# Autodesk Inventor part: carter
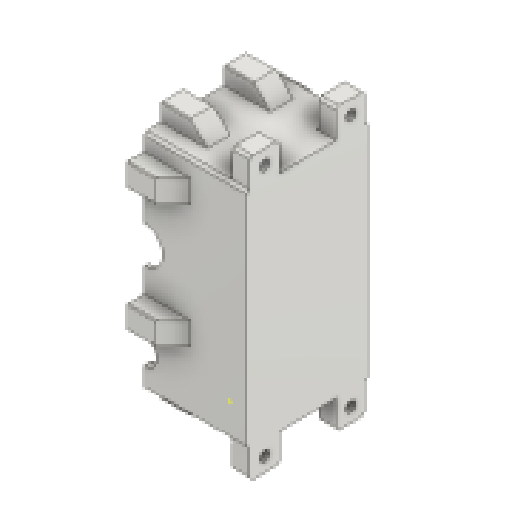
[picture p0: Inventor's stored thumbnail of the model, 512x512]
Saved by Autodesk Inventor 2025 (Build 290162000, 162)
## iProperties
Created: 2026-05
Part Number: carter
Material: Acciaio
Document SubType Name: Modeling
Designer: R5800u
Density: 7.85 g/cm^3
Appearance: Acciaio
Author: R5800u
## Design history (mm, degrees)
node "Piano di lavoro1"
sketch "Schizzo1"
  geometry: L1 (0, -58)-(160, -58); L2 (160, -58)-(160, 332); L3 (160, 332)-(0, 332); L4 (0, 332)-(0, -58); C1 r 12 at (0, 0) reference; C2 r 31 at (0, 0) reference; C3 r 45 at (0, 162) reference; A1 r 19.5 centre (0, 162) between (-18.561, 156.023) and (-18.547, 168.023) reference; 5 further points
  constraints: 8 end point, 2 parallel, 1 horizontal, 1 perpendicular
  dimensions: "d0" = 160 distance of L1.start L1.end; "d1" = 390 distance of L1.end L2.end
extrude "Estrusione1" new body sketch "Schizzo1" distance "d3" = 35; taper "d4" = 0 deg
node "Piano di lavoro2"
mirror "Speculare1"
sketch "Schizzo2"
  geometry: L1 (0, 390)-(35, 390) reference; L2 (210, 0)-(210, 390) reference; L3 (0, 390)-(210, 390); L4 (210, 390)-(210, 0); L5 (210, 0)-(0, 0); L6 (0, 0)-(0, 390); 3 further points
  constraints: 8 end point, 2 parallel, 1 horizontal, 1 perpendicular
extrude "Estrusione2" join sketch "Schizzo2" distance "d6" = 20; taper "d7" = 0 deg
sketch "Schizzo3"
  geometry: L1 (-175, 390)-(-35, 390) reference; L2 (-175, 390)-(-175, 0) reference; L3 (-35, 390)-(-175, 390); L4 (-175, 390)-(-175, 370); L5 (-175, 370)-(-35, 370); L6 (-35, 370)-(-35, 390); L7 (0, 0)-(-35, 0) reference; L8 (-35, 0)-(-175, 0); L9 (-175, 0)-(-175, 20); L10 (-175, 20)-(-35, 20); L11 (-35, 20)-(-35, 0); 2 further points
  constraints: 16 end point, 4 parallel, 2 horizontal, 2 perpendicular, 2 point on line
  dimensions: "d8" = 20 distance of L4.end L3.end; "d9" = 20 distance of L8.end L9.end
extrude "Estrusione3" join sketch "Schizzo3" stored distance "d10" = 20; taper "d11" = 0 deg
sketch "Schizzo4"
  geometry: L1 (0, 170)-(0, 45) reference; L2 (0, 170)-(-180, 170) reference; L3 (-180, -220)-(-180, 170) reference; L4 (0, -220)-(-180, -220) reference; L5 (0, -193)-(0, -220) reference; L6 (0, -45)-(0, -131) reference; L7 (0, 45)-(0, -45); C1 r 32.5 at (0, 0); A1 r 31 centre (0, -162) between (0, -131) and (0, -193) reference; A2 r 45 centre (0, 0) between (0, 45) and (0, -45) reference; 3 further points
  constraints: 2 end point, 1 centre point, 1 coincident, 1 vertical
  dimensions: "d12" = 65 diameter of C1
  node "Linea chiusa proiettata1"
node "Piano di lavoro3"
extrude "Estrusione4" join sketch "Schizzo4" stored distance "d13" = 10; taper "d14" = 0 deg
sketch "Schizzo5"
  geometry: L1 (0, 332)-(0, 194.5) reference; L2 (0, 332)-(-180, 332) reference; L3 (-180, -58)-(-180, 332) reference; L4 (0, -58)-(-180, -58) reference; L5 (0, -31)-(0, -58) reference; L6 (0, 31)-(0, 129.5) reference; L7 (0, 31)-(0, -31); C1 r 21 at (-1.789, 0); A1 r 31 centre (0, 0) between (0, 31) and (0, -31) reference; A2 r 32.5 centre (0, 162) between (0, 194.5) and (0, 129.5) reference; 3 further points
  constraints: 2 end point, 1 centre point, 1 collinear
  dimensions: "d15" = 42 diameter of C1
  node "Linea chiusa proiettata2"
node "Piano di lavoro4"
extrude "Estrusione5" join sketch "Schizzo5" stored distance "d16" = 10; taper "d17" = 0 deg
mirror "Speculare2"
chamfer "Smusso1" distance "d18" = 5; stored, may be unused: second distance "d19" = 2, angle "d20" = 45 deg
sketch "Schizzo6"
  geometry: L1 (-35, 120)-(-30, 125) reference; L2 (-35, 120)-(-35, -12.5) reference; L3 (-35, -12.5)-(-28, -12.5) reference; L4 (-28, 0)-(-28, -12.5) reference; L5 (-28, 0)-(0, 0) reference; L6 (0, 0)-(0, 105) reference; L7 (140, 105)-(0, 105) reference; L8 (140, 0)-(140, 105) reference; L9 (168, 0)-(140, 0) reference; L10 (168, 0)-(168, -12.5) reference; L11 (175, -12.5)-(168, -12.5) reference; L12 (175, 120)-(175, -12.5) reference; L13 (170, 125)-(175, 120) reference; L14 (170, 125)-(-30, 125) reference; L15 (175, -260)-(170, -265) reference; L16 (175, -227.924)-(175, -260) reference; L17 (175, -227.924)-(162, -227.924) reference; L18 (162, -227.924)-(162, -238) reference; L19 (162, -238)-(140, -238) reference; L20 (140, -245)-(140, -238) reference; L21 (0, -245)-(140, -245) reference; L22 (0, -245)-(0, -238) reference; L23 (-22, -238)-(0, -238) reference; L24 (-22, -227.924)-(-22, -238) reference; L25 (-35, -227.924)-(-22, -227.924) reference; L26 (-35, -260)-(-35, -227.924) reference; L27 (-30, -265)-(-35, -260) reference; L28 (170, -265)-(-30, -265) reference; L29 (175, -77.5)-(175, -186.076) reference; L30 (175, -77.5)-(168, -77.5) reference; L31 (168, -77.5)-(168, -90) reference; L32 (168, -90)-(140, -90) reference; L33 (140, -176)-(140, -90) reference; L34 (162, -176)-(140, -176) reference; L35 (162, -176)-(162, -186.076) reference; L36 (175, -186.076)-(162, -186.076) reference; L37 (-35, -186.076)-(-35, -77.5) reference; L38 (-35, -186.076)-(-22, -186.076) reference; L39 (-22, -176)-(-22, -186.076) reference; L40 (-22, -176)-(0, -176) reference; L41 (0, -176)-(0, -90) reference; L42 (-28, -90)-(0, -90) reference; L43 (-28, -77.5)-(-28, -90) reference; L44 (-35, -77.5)-(-28, -77.5) reference; L45 (125, 125)-(125, -265); L46 (-30, 125)-(170, 125) reference; L47 (70, 125)-(70, -265); L48 (15, 125)-(15, -265); L49 (175, 75)-(-35, 75); L50 (-35, -260)-(-35, 120) reference; L51 (145, 95)-(205, 95); L52 (205, 95)-(205, 55); L53 (205, 55)-(145, 55); L54 (145, 55)-(145, 95); L55 (145, 95)-(205, 55); L56 (205, 95)-(145, 55); L57 (145, -235)-(105, -235); L58 (105, -235)-(105, -295); L59 (105, -295)-(145, -295); L60 (145, -295)-(145, -235); L61 (145, -235)-(105, -295); L62 (105, -235)-(145, -295); L63 (35, -235)-(-5, -235); L64 (-5, -235)-(-5, -295)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; 16 further points
  constraints: 106 end point, 18 midpoint, 16 parallel, 11 perpendicular, 8 horizontal, 6 point on line, 2 symmetric about line
  dimensions: "d21" = 50 distance between parallel lines of L12 L45; "d22" = 50 distance between parallel lines of L14 L49; "d23" = 60 distance of L52.end L53.end; "d24" = 40 distance of L51.end L52.end; "d29" = 40 distance of L59.end L58.end; "d30" = 60 distance of L58.end L57.end; "d31" = 40 distance of L65.end L64.end; "d32" = 60 distance of L64.end L63.end; "d33" = 40 distance of L71.end L70.end; "d34" = 60 distance of L70.end L69.end; "d35" = 60 distance of L77.end L76.end; "d36" = 40 distance of L76.end L75.end; "d41" = 40 distance of L83.end L82.end; "d42" = 60 distance of L82.end L81.end; "d43" = 60 distance of L90.end L91.end; "d44" = 40 distance of L89.end L90.end; "d45" = 60 distance of L97.end L96.end; "d46" = 40 distance of L96.end L95.end; "d47" = 125 distance between parallel lines of L28 L88
extrude "Estrusione6" join sketch "Schizzo6" distance "d48" = 50; taper "d49" = 0 deg
chamfer "Smusso2" distance "d50" = 30; stored, may be unused: second distance "d51" = 2, angle "d52" = 45 deg
sketch "Schizzo7"
  geometry: L1 (-35, 120)-(-30, 125) reference; L2 (-35, 120)-(-35, 95) reference; L3 (-35, 95)-(-65, 95) reference; L4 (-65, 95)-(-65, 55) reference; L5 (-65, 55)-(-35, 55) reference; L6 (-35, 55)-(-35, -12.5) reference; L7 (-35, -12.5)-(-28, -12.5) reference; L8 (-28, 0)-(-28, -12.5) reference; L9 (-28, 0)-(0, 0) reference; L10 (0, 0)-(0, 105) reference; L11 (140, 105)-(0, 105) reference; L12 (140, 0)-(140, 105) reference; L13 (168, 0)-(140, 0) reference; L14 (168, 0)-(168, -12.5) reference; L15 (175, -12.5)-(168, -12.5) reference; L16 (175, 55)-(175, -12.5) reference; L17 (175, 55)-(205, 55) reference; L18 (205, 55)-(205, 95) reference; L19 (205, 95)-(175, 95) reference; L20 (175, 120)-(175, 95) reference; L21 (170, 125)-(175, 120) reference; L22 (170, 125)-(145, 125) reference; L23 (145, 125)-(145, 155) reference; L24 (145, 155)-(105, 155) reference; L25 (105, 155)-(105, 125) reference; L26 (105, 125)-(35, 125) reference; L27 (35, 125)-(35, 155) reference; L28 (35, 155)-(-5, 155) reference; L29 (-5, 155)-(-5, 125) reference; L30 (-5, 125)-(-30, 125) reference; L31 (-35, -186.076)-(-35, -160) reference; L32 (-35, -186.076)-(-22, -186.076) reference; L33 (-22, -176)-(-22, -186.076) reference; L34 (-22, -176)-(0, -176) reference; L35 (0, -176)-(0, -90) reference; L36 (-28, -90)-(0, -90) reference; L37 (-28, -77.5)-(-28, -90) reference; L38 (-35, -77.5)-(-28, -77.5) reference; L39 (-35, -120)-(-35, -77.5) reference; L40 (-35, -120)-(-65, -120) reference; L41 (-65, -120)-(-65, -160) reference; L42 (-65, -160)-(-35, -160) reference; L43 (-5, -265)-(35, -265) reference; L44 (175, -260)-(170, -265) reference; L45 (175, -227.924)-(175, -260) reference; L46 (175, -227.924)-(162, -227.924) reference; L47 (162, -227.924)-(162, -238) reference; L48 (162, -238)-(140, -238) reference; L49 (140, -245)-(140, -238) reference; L50 (0, -245)-(140, -245) reference; L51 (0, -245)-(0, -238) reference; L52 (-22, -238)-(0, -238) reference; L53 (-22, -227.924)-(-22, -238) reference; L54 (-35, -227.924)-(-22, -227.924) reference; L55 (-35, -260)-(-35, -227.924) reference; L56 (-30, -265)-(-35, -260) reference; L57 (-5, -265)-(-30, -265) reference; L58 (-5, -265)-(-5, -295) reference; L59 (-5, -295)-(35, -295) reference; L60 (35, -295)-(35, -265) reference; L61 (105, -265)-(35, -265) reference; L62 (105, -265)-(105, -295) reference; L63 (105, -295)-(145, -295) reference; L64 (145, -295)-(145, -265) reference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; 9 further points
  constraints: 16 end point, 8 midpoint, 2 parallel
hole "Foro1" sketch "Schizzo7" at (15, -280), (125, -280), (190, -140), (-50, -140), (-50, 75), (15, 140), (125, 140), (190, 75) diameter "d53" = 10.106; stored, may be unused: countersink angle "d57" = 82 deg, drill point angle "d59" = 118 deg; dims "d54" = 24, "d55" = 3.023, "d56" = 2, "d58" = 32.3
sketch "Schizzo8"
  geometry: L1 (160, 30)-(160, 170) reference; L2 (160, 100)-(144, 100); 1 further point
  constraints: 2 end point, 1 horizontal, 1 midpoint
  dimensions: "d60" = 16 distance of L2.start L2.end
hole "Foro2" sketch "Schizzo8" at (144, 100) diameter "d61" = 29.83494; stored, may be unused: countersink angle "d65" = 90 deg, drill point angle "d67" = 118 deg; dims "d62" = 64, "d63" = 4, "d64" = 2, "d66" = 73.3
chamfer "Smusso3" distance "d68" = 2; stored, may be unused: second distance "d69" = 2, angle "d70" = 45 deg
chamfer "Smusso4" distance "d71" = 0.4; stored, may be unused: second distance "d72" = 2, angle "d73" = 45 deg
sketch "Schizzo9"
  geometry: L1 (205, 390)-(210, 385) reference; L2 (205, 390)-(5, 390) reference; L3 (0, 385)-(5, 390) reference; L4 (0, 385)-(0, 5) reference; L5 (5, 0)-(0, 5) reference; L6 (5, 0)-(205, 0) reference; L7 (210, 5)-(205, 0) reference; L8 (210, 5)-(210, 385) reference; L9 (205, 0)-(155, 0); L10 (155, 0)-(155, -50); L11 (155, -50)-(205, -50); L12 (205, -50)-(205, 0); L13 (5, 0)-(55, 0); L14 (55, 0)-(55, -50); L15 (55, -50)-(5, -50); L16 (5, -50)-(5, 0); L17 (205, 390)-(155, 390); L18 (155, 390)-(155, 440); L19 (155, 440)-(205, 440); L20 (205, 440)-(205, 390); L21 (5, 390)-(55, 390); L22 (55, 390)-(55, 440); L23 (55, 440)-(5, 440); L24 (5, 440)-(5, 390); 5 further points
  constraints: 32 end point, 8 parallel, 4 horizontal, 4 perpendicular, 2 point on line
  dimensions: "d74" = 50 distance of L11.end L10.end; "d75" = 50 distance of L10.end L9.end; "d76" = 50 distance of L18.end L19.end; "d77" = 50 distance of L17.end L18.end; "d78" = 50 distance of L23.end L22.end; "d79" = 50 distance of L22.end L21.end
extrude "Estrusione7" join sketch "Schizzo9" distance "d80" = 30; taper "d81" = 0 deg
sketch "Schizzo10"
  geometry: 1 further point
sketch "Schizzo11"
  geometry: L1 (-205, 0)-(-205, -50) reference; L2 (-205, -50)-(-155, -50) reference; L3 (-155, -50)-(-155, 0) reference; L4 (-205, 0)-(-155, 0) reference; L5 (-155, 440)-(-205, 440) reference; L6 (-205, 440)-(-205, 390) reference; L7 (-155, 390)-(-205, 390) reference; L8 (-155, 390)-(-155, 440) reference; L9 (-5, 390)-(-5, 440) reference; L10 (-5, 440)-(-55, 440) reference; L11 (-55, 440)-(-55, 390) reference; L12 (-5, 390)-(-55, 390) reference; L13 (-55, -50)-(-5, -50) reference; L14 (-5, -50)-(-5, 0) reference; L15 (-55, 0)-(-5, 0) reference; L16 (-55, 0)-(-55, -50) reference; L17 (-205, 0)-(-155, -50); L18 (-55, -50)-(-5, 0); L19 (-155, 440)-(-205, 390); L20 (-55, 440)-(-5, 390); 5 further points
  constraints: 8 end point, 4 midpoint, 2 perpendicular, 1 parallel
hole "Foro3" sketch "Schizzo11" at (-180, -25), (-30, -25), (-180, 415), (-30, 415) diameter "d85" = 17.294; stored, may be unused: countersink angle "d89" = 90 deg, drill point angle "d91" = 118 deg; dims "d86" = 40, "d87" = 32, "d88" = 10, "d90" = 8
chamfer "Smusso6" distance "d92" = 5; stored, may be unused: second distance "d93" = 2, angle "d94" = 45 deg
fillet "Raccordo1" dims "d95" = 5
node "Solido1"
node "Riferimento1"
node "Riferimento2"
node "Riferimento3"
node "Riferimento4"
node "Linea chiusa proiettata3"
node "Linea chiusa proiettata4"
node "Linea chiusa proiettata5"
node "Linea chiusa proiettata6"
node "Linea chiusa proiettata7"
node "Linea chiusa proiettata8"
node "Linea chiusa proiettata9"
node "Linea chiusa proiettata10"
node "Linea chiusa proiettata11"
node "Linea chiusa proiettata12"
node "Linea chiusa proiettata13"
node "Linea chiusa proiettata14"
node "Linea chiusa proiettata15"
